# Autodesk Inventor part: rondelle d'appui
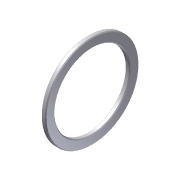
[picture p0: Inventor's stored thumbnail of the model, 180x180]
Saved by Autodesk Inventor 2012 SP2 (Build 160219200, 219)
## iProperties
Created: 2013-04
Part Number: rondelle d'appui
Material: Default
Document SubType Name: Modeling
Designer: papa
Density: 1 g/cm^3
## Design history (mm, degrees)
node "rondelle d'appui1"
sketch "Esquisse2"
  geometry: C1 r 19.15 at (0, 0) reference; C2 r 26.269 at (0, 0)
  constraints: 1 centre point, 1 coincident
extrude "Extrusion2" cut sketch "Esquisse2" distance "d2" = 0.1; taper "d3" = 0 deg
node "rondelle d'appui"
node "Base1"
